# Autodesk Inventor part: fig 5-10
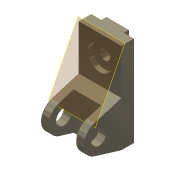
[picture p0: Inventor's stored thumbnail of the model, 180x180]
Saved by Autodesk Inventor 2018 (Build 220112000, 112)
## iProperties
Shininess: 65.0
Angle Display Precision: 2
Document Length Units: 11269
Document Angle Units: 11279
Document Time Units: 11290
Document Mass Units: 11283
Document Length Units Precision: 3
Document Angle Units Precision: 2
Compacted: False
Created: 2001-11
Part Number: fig 5-10
Document SubType Name: Modeling
Designer: Renu Muthoo
Density: 1 g/cm^3
Material: Generic
Appearance: Metal-Titanium (Polished)
Density: 0.0
Volumn: 0.0
Area: 0.0
PropertySet Name: Model Information
Control State: 0
Master: False
Checked Out: False
Author: Renu Muthoo
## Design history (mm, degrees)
node "Sketch1"
sketch "Sketch2"
  geometry: L1 (33.257, 104.664)-(33.257, -75.336); L2 (33.257, -75.336)-(8.257, -75.336); L3 (8.257, -75.336)-(-45.451, -59.045); L4 (-45.451, -1.628)-(8.257, 14.664); L5 (8.257, 14.664)-(8.257, 104.664); L6 (8.257, 104.664)-(33.257, 104.664); C1 r 15 at (-36.743, -30.336); A1 r 30 centre (-36.743, -30.336) between (-45.451, -1.628) and (-45.451, -59.045)
  constraints: 12 end point, 2 centre point, 2 equal length, 2 parallel, 2 point on circle, 2 tangent, 1 coincident, 1 perpendicular, 1 vertical
  dimensions: "d0" = 180 distance of L1.start L1.end; "d1" = 30 radius of A1; "d2" = 25 distance of L5.end L1.start; "d3" = 45 distance from line of L2 A1.centre; "d4" = 70 distance from line of L1 A1.centre; "d5" = 30 diameter of C1
extrude "Extrusion1" new body sketch "Sketch2" distance "d6" = 85; taper "d7" = 0 deg
workplane "Work Plane1"
sketch "Sketch3"
  geometry: L1 (15, 62.364)-(70, 62.364); L2 (70, 62.364)-(70, -52.386); L3 (70, -52.386)-(15, -52.386); L4 (15, -52.386)-(15, 62.364); L5 (0, -45)-(0, -28.708) reference
  constraints: 8 end point, 2 parallel, 1 horizontal, 1 perpendicular
  dimensions: "d8" = 55 distance of L1.start L1.end; "d9" = 15 distance between parallel lines of L5 L4
extrude "Extrusion2" cut sketch "Sketch3" distance "d10" = 50; taper "d11" = 0 deg
sketch "Sketch4"
  geometry: L1 (0, 25)-(85, 25) reference; L2 (0, 0)-(0, 25) reference; L3 (20, 25)-(65, 25); L4 (65, 25)-(65, 35); L5 (65, 35)-(20, 35); L6 (20, 35)-(20, 25)
  constraints: 8 end point, 2 parallel, 1 horizontal, 1 perpendicular, 1 point on line
  dimensions: "d12" = 45 distance of L4.end L5.end; "d13" = 10 distance of L3.end L4.end; "d14" = 20 distance between parallel lines of L2 L6
extrude "Extrusion3" join sketch "Sketch4" stored distance "d15" = 50; taper "d16" = 0 deg
sketch "Sketch5"
  geometry: L1 (85, 0)-(85, 90) reference; L2 (0, 90)-(85, 90) reference; 1 further point
  dimensions: "d17" = 42 distance from line of L2 point (42.5, 48); "d18" = 42.5 distance from line of L1 point (42.5, 48)
hole "Hole1" sketch "Sketch5" at (42.5, 48) diameter "d19" = 20; stored, may be unused: countersink angle "d23" = 82 deg, drill point angle "d25" = 118 deg; dims "d20" = 6, "d21" = 50, "d22" = 10, "d24" = 8
workplane "Work Plane4"
body "Solid1"
